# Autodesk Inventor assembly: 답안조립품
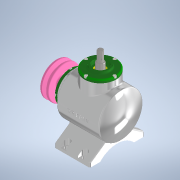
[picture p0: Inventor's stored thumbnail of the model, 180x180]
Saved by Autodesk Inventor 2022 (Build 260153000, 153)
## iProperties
Created: 2023-04
Part Number: 답안조립품
Document SubType Name: Assembly
Designer: Admin
Author: Admin
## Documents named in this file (17)
- C:\Users\Admin\Desktop\730411V1001\답안조립품.iam
- C:\Users\Admin\Desktop\730411V1001\본체.ipt
- C:\Users\Admin\Desktop\730411V1001\커버.ipt
- C:\Users\Admin\Desktop\730411V1001\베어링 6203.ipt
- C:\Users\Admin\Desktop\730411V1001\오일실 17 x 32 x 8.ipt
- C:\Users\Admin\Desktop\730411V1001\메인 축.ipt
- 메인 축.ipt
- C:\Users\Admin\Desktop\730411V1001\키 5 x 5 x 14.ipt
- C:\Users\Admin\Desktop\730411V1001\메인 베벨기어.ipt
- C:\Users\Admin\Desktop\730411V1001\서브 축.ipt
- 서브 축.ipt
- C:\Users\Admin\Desktop\730411V1001\키 4 x 4 x 14.ipt
- C:\Users\Admin\Desktop\730411V1001\서브 베벨기어.ipt
- C:\Users\Admin\Desktop\730411V1001\V-벨트풀리.ipt
- C:\Users\Admin\Desktop\730411V1001\와셔 4 x 16.ipt
- C:\Users\Admin\Desktop\730411V1001\육각볼트 M4 x 8.ipt
- C:\Users\Admin\Desktop\730411V1001\볼트 M4 x 10.ipt
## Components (1 placed, 1 different names)
1. V-벨트풀리:1
